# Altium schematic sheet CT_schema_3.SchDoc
size 176 x 147 mm
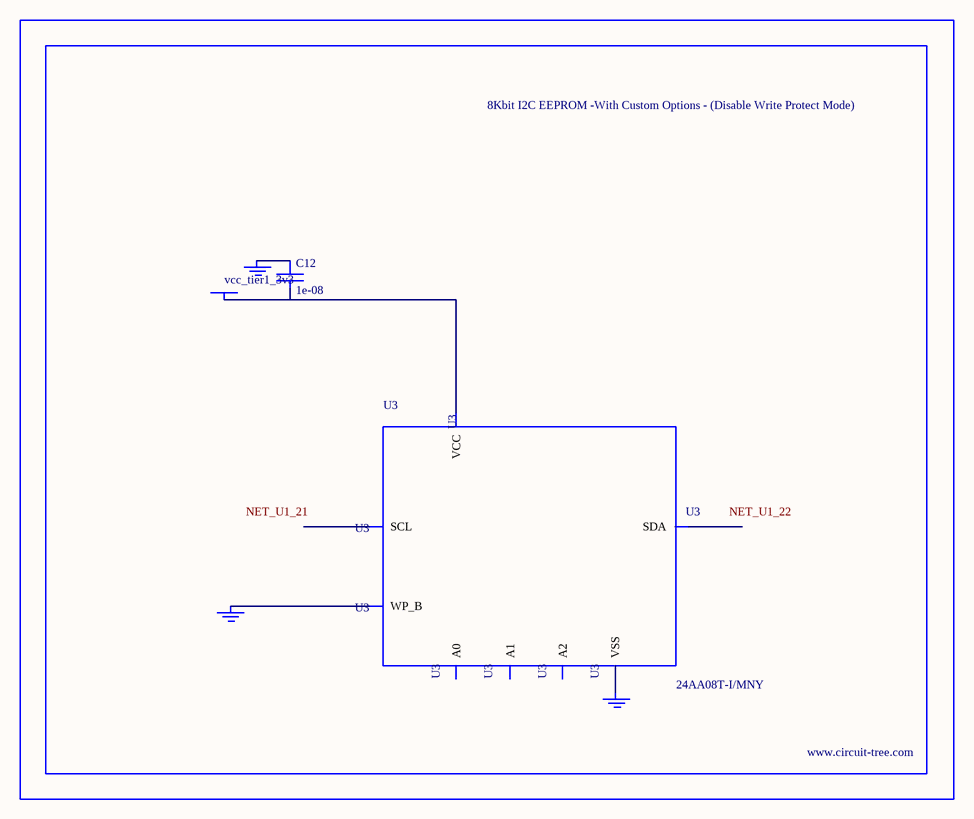
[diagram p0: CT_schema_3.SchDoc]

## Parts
BORDER2  (no value)
C12  1e-08  [C0402]
GND_INSTANCE_2_0  (no value)
GND_INSTANCE_2_1  (no value)
GND_INSTANCE_2_2  (no value)
POWER_INSTANCE_2_0  vcc_tier1_3v3
U3  24AA08T-I/MNY  [TDFN-8/6MM]

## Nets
NetC12_1: C12.1 GND_INSTANCE_2_1.0(GND)
NetC12_2: C12.2 POWER_INSTANCE_2_0.0(PWR) U3.8(VCC)
NetGND_INSTANCE_2_0_0: GND_INSTANCE_2_0.0(GND) U3.7(WP_B)
NetGND_INSTANCE_2_2_0: GND_INSTANCE_2_2.0(GND) U3.4(VSS)

Not connected (* = marked no-connect by the designer): U3 1(A0) 2(A1) 3(A2) 5(SDA) 6(SCL)

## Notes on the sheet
- Labels drawn without touching a wire or pin: NET_U1_21, NET_U1_22

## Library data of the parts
BORDER2 = BORDER_PAGE2
C12 = C0402C103K3RAC
GND_INSTANCE_2_0-GND_INSTANCE_2_2 = GND
POWER_INSTANCE_2_0 = PWR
